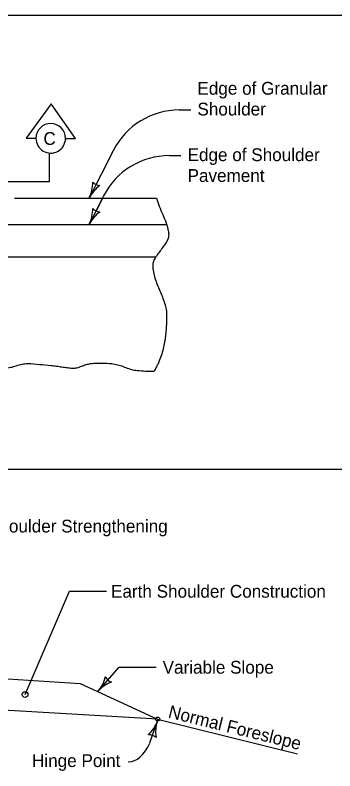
# Model space of a CAD drawing. Extents: x 10133 to 81668, y 7924 to 12229.
# Drawn here: x 11801 to 12201, y 11284 to 12229 of the extents above; entities that cross this region are included whole.
import ezdxf

# ---------------------------------------------------------------- set-up
doc = ezdxf.new("R2010")
doc.units = 0
for name, color, linetype in [('dsnTextFinalPlan', 7, 'Continuous'), ('Level 1', 7, 'Continuous'), ('Level 4', 7, 'Continuous'), ('Level 6', 7, 'Continuous'), ('Level 7', 7, 'Continuous'), ('SheetText', 7, 'Continuous')]:
    doc.layers.add(name, color=color, linetype=linetype)

msp = doc.modelspace()

# ---------------------------------------------------------------- linework, layer by layer
at = {"layer": 'dsnTextFinalPlan'}
for p, q in [((11800.44, 12000.48), (11978.32, 12000.48)), ((11910.14, 11999.3), (11893.9, 11967.5)), ((10342.6, 11967.5), (11990.07, 11967.5)), ((10363.81, 11926.85), (11977.6, 11926.85)), ((11747.93, 11402.08), (11882.68, 11393.7)), ((11882.68, 11393.7), (11979.73, 11349.21)), ((11979.73, 11349.21), (11403.63, 11382.43)), ((11979.73, 11349.21), (12154.72, 11305.9))]:
    msp.add_line(p, q, dxfattribs=at)
msp.add_ellipse((11979.73, 11349.21), major_axis=(2.58, 0), ratio=0.913811, dxfattribs=at)
for points in [[(11978.32, 12000.48), (11981.78, 11990.35), (11986.15, 11979.96), (11990.31, 11969.33), (11991.96, 11963.92), (11993.14, 11958.45), (11993.52, 11953.07), (11993.31, 11951.7), (11992.99, 11950.35), (11991.88, 11947.77), (11984.95, 11937.27), (11983.04, 11934.62), (11981.08, 11932.01), (11979.13, 11929.38), (11977.23, 11926.71), (11974.6, 11921.33), (11973.59, 11915.85), (11973.79, 11912), (11974.36, 11908.13), (11976.37, 11900.36), (11982.43, 11884.71), (11988.42, 11868.99), (11990.35, 11861.13), (11991, 11853.3), (11990.78, 11844.7), (11990.29, 11836.05), (11989.42, 11827.33), (11988.8, 11822.99), (11988.07, 11818.65), (11986.09, 11809.86), (11983.36, 11801.25), (11979.77, 11792.61), (11977.62, 11788.31), (11976.44, 11786.16), (11975.2, 11784.02)], [(11695.49, 11787.77), (11697.49, 11787.88), (11705.06, 11788.36), (11712.63, 11789.02), (11720.18, 11789.83), (11727.71, 11790.73), (11732.46, 11791.73), (11737.14, 11793.17), (11741.81, 11794.53), (11744.16, 11795.02), (11746.53, 11795.3), (11753.06, 11795.28), (11759.66, 11794.62), (11766.24, 11793.59), (11772.76, 11792.44), (11776.77, 11791.5), (11780.74, 11790.3), (11784.72, 11789.17), (11788.73, 11788.45), (11792.27, 11788.42), (11795.82, 11788.92), (11802.93, 11790.85), (11810.06, 11792.86), (11817.24, 11793.58), (11831.77, 11792.61), (11846.32, 11791.3), (11853.04, 11790.48), (11859.74, 11789.49), (11866.44, 11788.55), (11873.12, 11787.88), (11878.87, 11788.45), (11884.55, 11790.27), (11890.21, 11792.33), (11895.93, 11793.58), (11903.43, 11794.09), (11911.03, 11794.22), (11922.41, 11793.53), (11926.15, 11793.01), (11933.17, 11791.19), (11940.06, 11788.63), (11946.98, 11786.26), (11954.09, 11785.03), (11975.2, 11784.02)]]:
    msp.add_spline(points, degree=3, dxfattribs=at)
at = {"layer": 'Level 1'}
msp.add_line((10147.13, 12229.21), (13242.82, 12229.21), dxfattribs=at)
at = {"layer": 'Level 4'}
msp.add_line((12302.71, 11661.22), (10147.13, 11661.22), dxfattribs=at)
msp.add_circle((11813.85, 11379.81), 3.54, dxfattribs=at)
msp.add_circle((11813.85, 11379.81), 3.54, dxfattribs=at)
at = {"layer": 'Level 6'}
for p, q in [((12006.74, 12110.62), (12021.05, 12110.62)), ((12006.74, 12110.62), (12021.05, 12110.62)), ((11924.43, 12060.25), (11893.9, 12000.48)), ((11924.43, 12060.25), (11893.9, 12000.48)), ((11994.44, 12053.56), (12008.74, 12053.56)), ((11994.44, 12053.56), (12008.74, 12053.56)), ((11912.13, 12003.19), (11893.9, 11967.5)), ((11912.13, 12003.19), (11893.9, 11967.5))]:
    msp.add_line(p, q, dxfattribs=at)
for centre, radius, start, end in [((12006.74, 12018.19), 92.43, 90, 152.9341), ((12006.74, 12018.19), 92.43, 90, 152.9341), ((11994.44, 11961.13), 92.43, 90, 152.9341), ((11994.44, 11961.13), 92.43, 90, 152.9341), ((11856.05, 12019.82), 42.5, 332.9341, 1.00659), ((11856.05, 12019.82), 42.5, 332.9341, 1.00659), ((11910.11, 12032.22), 16.42, 225.20075, 260.66745), ((11910.11, 12032.22), 16.42, 225.20075, 260.66745), ((11931.74, 11981.15), 42.5, 124.86161, 152.9341), ((11931.74, 11981.15), 42.5, 124.86161, 152.9341), ((11856.05, 11986.84), 42.5, 332.9341, 1.00659), ((11856.05, 11986.84), 42.5, 332.9341, 1.00659), ((11931.74, 11948.17), 42.5, 124.86161, 152.9341), ((11931.74, 11948.17), 42.5, 124.86161, 152.9341), ((11910.11, 11999.24), 16.42, 225.20075, 260.66745), ((11910.11, 11999.24), 16.42, 225.20075, 260.66745)]:
    msp.add_arc(centre, radius, start, end, dxfattribs=at)
at = {"layer": 'Level 7'}
for p, q in [((11844.49, 12021.32), (11844.49, 12056.76)), ((11844.49, 12021.32), (11844.49, 12056.76)), ((11756.39, 12021.32), (11844.49, 12021.32)), ((11756.39, 12021.32), (11844.49, 12021.32))]:
    msp.add_line(p, q, dxfattribs=at)
msp.add_lwpolyline([(11864.46, 12075.03), (11876.78, 12074.92), (11846.37, 12118.33), (11815.17, 12075.48), (11827.49, 12075.37)], dxfattribs=at)
for start, end in [(359.4792, 179.47754), (179.47754, 359.4792)]:
    msp.add_arc((11845.97, 12075.2), 18.49, start, end, dxfattribs=at)
at = {"layer": 'SheetText'}
for p, q in [((11813.85, 11379.81), (11869.57, 11508.94)), ((11869.57, 11508.94), (11915.94, 11508.94)), ((11904.87, 11383.53), (11931.46, 11413.95)), ((11931.46, 11413.95), (11977.83, 11413.95)), ((11969.97, 11319.29), (11979.44, 11346.86))]:
    msp.add_line(p, q, dxfattribs=at)
for centre, radius, start, end in [((11872.87, 11411.5), 42.5, 318.84535, 346.91784), ((11936.87, 11355.56), 42.5, 110.77286, 138.84535), ((11928.32, 11410.36), 16.42, 211.112, 246.5787), ((11939.24, 11360.67), 42.5, 312.97879, 341.05128), ((12019.64, 11333.06), 42.5, 161.05128, 189.12377), ((11967.87, 11313.16), 16.42, 53.31793, 88.78463)]:
    msp.add_arc(centre, radius, start, end, dxfattribs=at)
msp.add_ellipse((11942.88, 11357.14), major_axis=(0, 61.47), ratio=0.559383, start_param=3.141593, end_param=4.048985, dxfattribs=at)

# ---------------------------------------------------------------- texts
at = {"layer": 'Level 6'}
for s, p in [('Edge of Granular', (12029.48, 12129.74)), ('Edge of Granular', (12029.48, 12129.74)), ('Shoulder', (12029.48, 12103.74)), ('Shoulder', (12029.48, 12103.74)), ('Edge of Shoulder', (12017.18, 12046.68)), ('Edge of Shoulder', (12017.18, 12046.68)), ('Pavement', (12017.18, 12020.68)), ('Pavement', (12017.18, 12020.68))]:
    msp.add_text(s, height=16, dxfattribs=at).set_placement(p)
at = {"layer": 'Level 7'}
msp.add_text('C', height=16, dxfattribs=at).set_placement((11836.86, 12066.97))
msp.add_text('C', height=16, dxfattribs=at).set_placement((11836.86, 12066.97))
at = {"layer": 'SheetText'}
for s, p in [('Edge of Shoulder Strengthening', (11687.79, 11582.44)), ('Earth Shoulder Construction', (11921.41, 11500.94)), ('Variable Slope', (11985.94, 11405.95)), ('Hinge Point', (11822.54, 11289.26))]:
    msp.add_text(s, height=16, dxfattribs=at).set_placement(p)
msp.add_text('Normal Foreslope', height=16, rotation=346.0988, dxfattribs=at).set_placement((11991.99, 11351.26))

doc.saveas('drawing.dxf')
